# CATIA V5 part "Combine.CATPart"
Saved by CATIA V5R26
Part number: Combine
Bounding box of the stored display mesh (mm): x -80.825 to 220.996, y -154.06 to 514.937, z -58.81 to 90.824
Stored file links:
  D:\LinkedIn Learning\NURBS\CATIA\Class Parts\Combine.CATPart
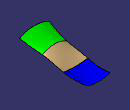
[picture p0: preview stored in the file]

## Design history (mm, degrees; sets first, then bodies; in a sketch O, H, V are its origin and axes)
AxisSystem1: origin (0, 0, 0), X (1, 0, 0), Y (0, 1, 0), Z (0, 0, 1)
Set1
  DatumSurface1 to DatumSurface3
Body1 (main body)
